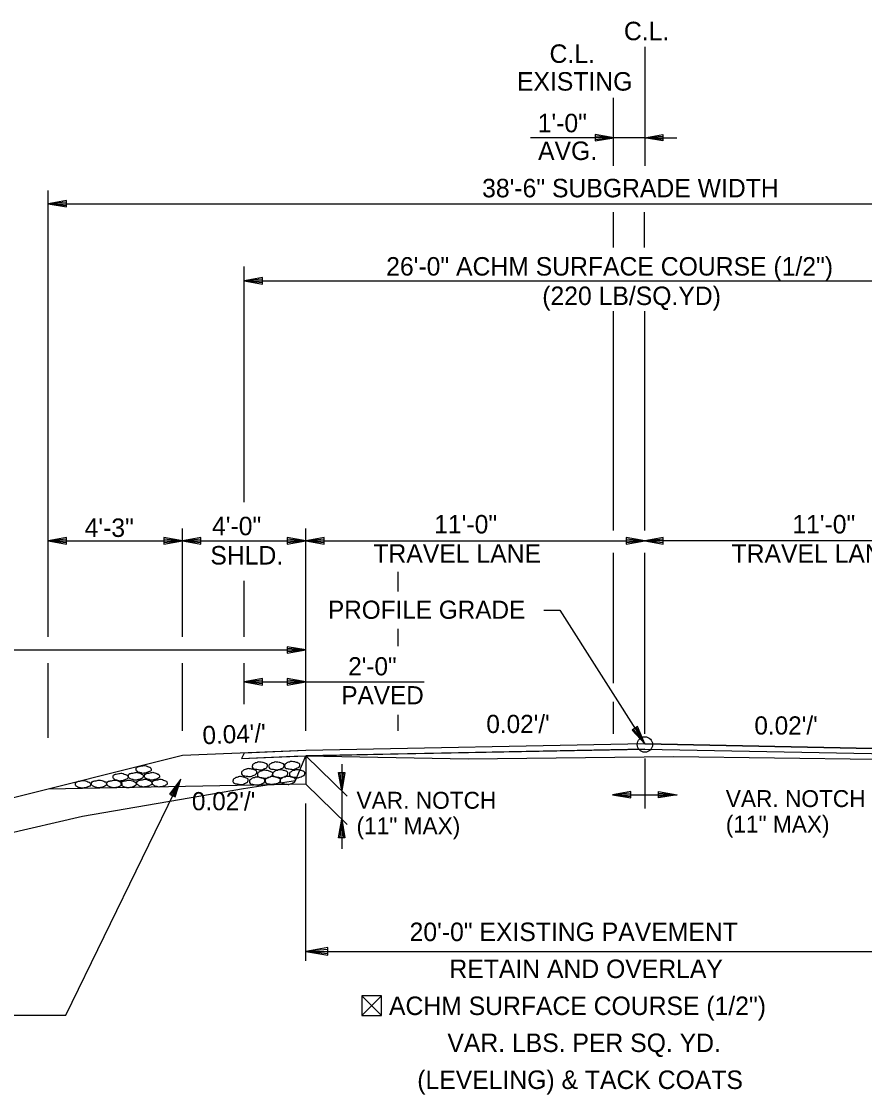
# Model space of a CAD drawing. Extents: x 1461846 to 1462006, y 1686171 to 1686805.
# Drawn here: x 1461905.82 to 1461933.18, y 1686235.49 to 1686270.31 of the extents above; entities that cross this region are included whole.
import ezdxf

# ---------------------------------------------------------------- set-up
doc = ezdxf.new("R2010")
doc.units = 0
for name, color, linetype in [('1', 7, 'Continuous'), ('10', 7, 'Continuous'), ('19', 7, 'Continuous'), ('20', 7, 'Continuous'), ('42', 7, 'Continuous'), ('Level 1', 7, 'Continuous'), ('Level 7', 7, 'Continuous'), ('Level 9', 7, 'Continuous'), ('R_Draft', 7, 'Continuous')]:
    doc.layers.add(name, color=color, linetype=linetype)

# ---------------------------------------------------------------- blocks, each defined once
blk = doc.blocks.new('ROCKS')
at = {"layer": '1'}
blk.add_spline([(0.013, 0.06), (0.053, 0.053), (0.107, 0.033), (0.133, 0.013), (0.133, -0.007), (0.12, -0.033), (0.107, -0.04), (0.073, -0.053), (0.033, -0.067), (0.013, -0.067), (-0.02, -0.06), (-0.06, -0.053), (-0.087, -0.047), (-0.113, -0.02), (-0.113, -0.007), (-0.107, 0.02), (-0.087, 0.033), (-0.067, 0.047), (-0.033, 0.053), (-0.02, 0.06), (0.013, 0.06)], degree=3, dxfattribs=at)
blk = doc.blocks.new('4TO1 ABC')
at = {"layer": '1', "xscale": 0.1312491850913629, "yscale": 0.1312491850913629, "rotation": 180}
for p in [(0.00175, -0.00875), (-0.016625, -0.023625), (0.018375, -0.023625), (0.051625, -0.025375), (-0.03325, -0.0385), (0, -0.0385), (0.034125, -0.04025), (0.06475, -0.04025), (0.098, -0.04025), (0.133, -0.041125)]:
    blk.add_blockref('ROCKS', p, dxfattribs=at)

msp = doc.modelspace()

# ---------------------------------------------------------------- linework, layer by layer
at = {"layer": '10'}
for p, q in [((1461916.861, 1686238.694), (1461917.502, 1686238.053)), ((1461917.502, 1686238.694), (1461916.861, 1686238.053))]:
    msp.add_line(p, q, dxfattribs=at)
msp.add_lwpolyline([(1461917.253, 1686238.053), (1461917.502, 1686238.053), (1461917.502, 1686238.694), (1461916.861, 1686238.694), (1461916.861, 1686238.053), (1461917.242, 1686238.053)], dxfattribs=at)
at = {"layer": '19'}
for p, q in [((1461926.058, 1686265.626), (1461926.058, 1686269.495)), ((1461907.286, 1686264.503), (1461906.686, 1686264.398)), ((1461906.686, 1686264.398), (1461945.406, 1686264.398)), ((1461906.686, 1686264.398), (1461907.286, 1686264.293)), ((1461907.286, 1686264.448), (1461906.846, 1686264.413)), ((1461906.846, 1686264.383), (1461907.286, 1686264.343)), ((1461907.286, 1686264.293), (1461907.286, 1686264.503)), ((1461926.034, 1686262.982), (1461926.034, 1686264.129)), ((1461913.646, 1686262.003), (1461913.046, 1686261.898)), ((1461913.046, 1686261.898), (1461939.046, 1686261.898)), ((1461913.046, 1686261.898), (1461913.646, 1686261.793)), ((1461913.646, 1686261.948), (1461913.206, 1686261.913)), ((1461913.206, 1686261.883), (1461913.646, 1686261.843)), ((1461913.646, 1686261.793), (1461913.646, 1686262.003)), ((1461907.286, 1686253.562), (1461906.686, 1686253.457)), ((1461907.286, 1686253.507), (1461906.846, 1686253.472)), ((1461907.286, 1686253.352), (1461907.286, 1686253.562)), ((1461910.446, 1686253.562), (1461910.446, 1686253.352)), ((1461911.046, 1686253.457), (1461910.446, 1686253.562)), ((1461910.886, 1686253.472), (1461910.446, 1686253.507)), ((1461911.646, 1686253.562), (1461911.046, 1686253.457)), ((1461911.646, 1686253.507), (1461911.206, 1686253.472)), ((1461911.646, 1686253.352), (1461911.646, 1686253.562)), ((1461914.446, 1686253.562), (1461914.446, 1686253.352)), ((1461915.046, 1686253.457), (1461914.446, 1686253.562)), ((1461914.886, 1686253.472), (1461914.446, 1686253.507)), ((1461915.646, 1686253.562), (1461915.046, 1686253.457)), ((1461915.646, 1686253.507), (1461915.206, 1686253.472)), ((1461915.646, 1686253.352), (1461915.646, 1686253.562)), ((1461925.446, 1686253.562), (1461925.446, 1686253.352)), ((1461926.046, 1686253.457), (1461925.446, 1686253.562)), ((1461925.886, 1686253.472), (1461925.446, 1686253.507)), ((1461926.646, 1686253.562), (1461926.046, 1686253.457)), ((1461926.646, 1686253.507), (1461926.206, 1686253.472)), ((1461926.646, 1686253.352), (1461926.646, 1686253.562)), ((1461906.686, 1686253.457), (1461907.286, 1686253.352)), ((1461906.846, 1686253.442), (1461907.286, 1686253.402)), ((1461910.446, 1686253.352), (1461911.046, 1686253.457)), ((1461910.446, 1686253.402), (1461910.886, 1686253.442)), ((1461911.046, 1686253.457), (1461911.646, 1686253.352)), ((1461911.206, 1686253.442), (1461911.646, 1686253.402)), ((1461914.446, 1686253.352), (1461915.046, 1686253.457)), ((1461914.446, 1686253.402), (1461914.886, 1686253.442)), ((1461915.046, 1686253.457), (1461915.646, 1686253.352)), ((1461915.206, 1686253.442), (1461915.646, 1686253.402)), ((1461925.446, 1686253.352), (1461926.046, 1686253.457)), ((1461925.446, 1686253.402), (1461925.886, 1686253.442)), ((1461926.046, 1686253.457), (1461926.646, 1686253.352)), ((1461926.206, 1686253.442), (1461926.646, 1686253.402)), ((1461914.446, 1686250.022), (1461914.446, 1686249.812)), ((1461915.046, 1686249.917), (1461914.446, 1686250.022)), ((1461914.886, 1686249.932), (1461914.446, 1686249.967)), ((1461914.446, 1686249.812), (1461915.046, 1686249.917)), ((1461914.446, 1686249.862), (1461914.886, 1686249.902)), ((1461913.646, 1686248.986), (1461913.046, 1686248.881)), ((1461913.646, 1686248.776), (1461913.646, 1686248.986)), ((1461914.446, 1686248.986), (1461914.446, 1686248.776)), ((1461915.046, 1686248.881), (1461914.446, 1686248.986)), ((1461913.046, 1686248.881), (1461918.889, 1686248.881)), ((1461913.046, 1686248.881), (1461913.646, 1686248.776)), ((1461913.646, 1686248.931), (1461913.206, 1686248.896)), ((1461913.206, 1686248.866), (1461913.646, 1686248.826)), ((1461914.886, 1686248.896), (1461914.446, 1686248.931)), ((1461914.446, 1686248.776), (1461915.046, 1686248.881)), ((1461914.446, 1686248.826), (1461914.886, 1686248.866)), ((1461925.807, 1686247.428), (1461925.632, 1686247.314)), ((1461925.632, 1686247.314), (1461926.046, 1686246.868)), ((1461925.672, 1686247.336), (1461925.946, 1686246.995)), ((1461925.968, 1686247.007), (1461925.764, 1686247.395)), ((1461926.046, 1686246.868), (1461925.807, 1686247.428)), ((1461913.046, 1686246.568), (1461912.961, 1686246.398)), ((1461913.046, 1686246.568), (1461912.961, 1686246.398)), ((1461915.046, 1686246.648), (1461913.046, 1686246.568)), ((1461926.046, 1686246.868), (1461915.046, 1686246.648)), ((1461926.046, 1686246.701), (1461915.046, 1686246.481)), ((1461937.046, 1686246.648), (1461926.046, 1686246.868)), ((1461926.046, 1686246.701), (1461937.046, 1686246.481)), ((1461912.961, 1686246.398), (1461915.046, 1686246.481)), ((1461915.046, 1686246.481), (1461915.046, 1686245.565)), ((1461916.108, 1686245.939), (1461916.318, 1686245.939)), ((1461916.213, 1686245.339), (1461916.108, 1686245.939)), ((1461916.198, 1686245.499), (1461916.158, 1686245.939)), ((1461916.318, 1686245.939), (1461916.213, 1686245.339)), ((1461916.263, 1686245.939), (1461916.228, 1686245.499)), ((1461907.262, 1686238.068), (1461910.99, 1686245.726)), ((1461910.99, 1686245.726), (1461910.626, 1686245.238)), ((1461910.907, 1686245.59), (1461910.675, 1686245.216)), ((1461910.769, 1686245.168), (1461910.932, 1686245.577)), ((1461910.813, 1686245.145), (1461910.99, 1686245.726)), ((1461910.626, 1686245.238), (1461910.813, 1686245.145)), ((1461916.108, 1686243.822), (1461916.213, 1686244.422)), ((1461916.163, 1686243.822), (1461916.198, 1686244.262)), ((1461916.213, 1686244.422), (1461916.318, 1686243.822)), ((1461916.228, 1686244.262), (1461916.268, 1686243.822)), ((1461916.318, 1686243.822), (1461916.108, 1686243.822)), ((1461903.064, 1686238.068), (1461907.262, 1686238.068))]:
    msp.add_line(p, q, dxfattribs=at)
for points in [[(1461922.775, 1686251.211), (1461923.293, 1686251.211), (1461926.046, 1686246.868)], [(1461915.046, 1686246.481), (1461918.046, 1686246.541), (1461926.046, 1686246.701)], [(1461912.961, 1686246.398), (1461913.683, 1686246.427), (1461914.667, 1686246.466), (1461915.046, 1686246.481)]]:
    msp.add_lwpolyline(points, dxfattribs=at)
msp.add_circle((1461926.05, 1686246.849), 0.25, dxfattribs=at)
at = {"layer": '20'}
for p, q in [((1461915.046, 1686246.481), (1461916.39, 1686245.166)), ((1461915.046, 1686245.565), (1461916.39, 1686244.249)), ((1461915.046, 1686239.832), (1461915.046, 1686244.931)), ((1461915.761, 1686240.257), (1461915.046, 1686240.132)), ((1461915.046, 1686240.132), (1461915.761, 1686240.006)), ((1461915.046, 1686240.132), (1461935.046, 1686240.132)), ((1461915.761, 1686240.191), (1461915.237, 1686240.149)), ((1461915.237, 1686240.114), (1461915.761, 1686240.066)), ((1461915.761, 1686240.006), (1461915.761, 1686240.257))]:
    msp.add_line(p, q, dxfattribs=at)
msp.add_lwpolyline([(1461916.213, 1686246.215), (1461916.213, 1686243.465)], dxfattribs=at)
at = {"layer": '42'}
for p, q in [((1461926.046, 1686246.399), (1461926.046, 1686244.767)), ((1461925.598, 1686245.324), (1461924.998, 1686245.219)), ((1461924.998, 1686245.219), (1461925.598, 1686245.114)), ((1461924.998, 1686245.219), (1461927.093, 1686245.219)), ((1461925.598, 1686245.269), (1461925.158, 1686245.234)), ((1461925.158, 1686245.204), (1461925.598, 1686245.164)), ((1461925.598, 1686245.114), (1461925.598, 1686245.324)), ((1461926.493, 1686245.114), (1461926.493, 1686245.324)), ((1461926.493, 1686245.324), (1461927.093, 1686245.219)), ((1461926.493, 1686245.269), (1461926.933, 1686245.234)), ((1461927.093, 1686245.219), (1461926.493, 1686245.114)), ((1461926.933, 1686245.204), (1461926.493, 1686245.164))]:
    msp.add_line(p, q, dxfattribs=at)
at = {"layer": 'Level 7'}
for p, q in [((1461926.045, 1686254.861), (1461926.045, 1686260.908)), ((1461926.045, 1686253.792), (1461926.045, 1686254.861)), ((1461926.045, 1686247.189), (1461926.045, 1686253.071))]:
    msp.add_line(p, q, dxfattribs=at)
at = {"layer": 'Level 9'}
for p, q in [((1461906.686, 1686250.346), (1461906.686, 1686264.824)), ((1461913.046, 1686255.675), (1461913.046, 1686262.366)), ((1461906.686, 1686256.912), (1461906.686, 1686258.245)), ((1461913.046, 1686254.714), (1461913.046, 1686255.675)), ((1461906.686, 1686250.346), (1461906.686, 1686254.697)), ((1461911.046, 1686250.346), (1461911.046, 1686253.86)), ((1461915.046, 1686247.293), (1461915.046, 1686253.86)), ((1461906.686, 1686253.457), (1461915.046, 1686253.457)), ((1461915.046, 1686253.457), (1461926.046, 1686253.457)), ((1461937.046, 1686253.457), (1461926.046, 1686253.457)), ((1461913.046, 1686250.346), (1461913.046, 1686252.159)), ((1461918.046, 1686251.815), (1461918.046, 1686252.456)), ((1461918.046, 1686250.043), (1461918.046, 1686250.607)), ((1461891.046, 1686249.917), (1461915.046, 1686249.917)), ((1461906.686, 1686247.061), (1461906.686, 1686249.485)), ((1461911.046, 1686247.293), (1461911.046, 1686249.485)), ((1461913.046, 1686248.152), (1461913.046, 1686249.485)), ((1461918.046, 1686247.293), (1461918.046, 1686247.806))]:
    msp.add_line(p, q, dxfattribs=at)
at = {"layer": 'R_Draft'}
for p, q in [((1461925.034, 1686265.626), (1461925.034, 1686267.832)), ((1461924.034, 1686266.54), (1461922.334, 1686266.54)), ((1461926.034, 1686266.54), (1461924.034, 1686266.54)), ((1461924.44, 1686266.645), (1461924.44, 1686266.435)), ((1461925.04, 1686266.54), (1461924.44, 1686266.645)), ((1461924.88, 1686266.555), (1461924.44, 1686266.59)), ((1461924.44, 1686266.435), (1461925.04, 1686266.54)), ((1461924.44, 1686266.485), (1461924.88, 1686266.525)), ((1461926.034, 1686266.54), (1461926.634, 1686266.645)), ((1461926.634, 1686266.435), (1461926.034, 1686266.54)), ((1461926.034, 1686266.54), (1461927.087, 1686266.54)), ((1461926.194, 1686266.555), (1461926.634, 1686266.59)), ((1461926.634, 1686266.485), (1461926.194, 1686266.525)), ((1461926.634, 1686266.645), (1461926.634, 1686266.435)), ((1461925.034, 1686262.982), (1461925.034, 1686264.129)), ((1461925.034, 1686254.861), (1461925.034, 1686260.908)), ((1461925.034, 1686253.792), (1461925.034, 1686254.861)), ((1461925.034, 1686248.84), (1461925.034, 1686253.071)), ((1461925.034, 1686247.189), (1461925.034, 1686248.232)), ((1461915.046, 1686246.648), (1461911.046, 1686246.488)), ((1461926.046, 1686246.868), (1461915.046, 1686246.648)), ((1461926.046, 1686246.868), (1461937.046, 1686246.648)), ((1461926.046, 1686246.701), (1461937.046, 1686246.481)), ((1461911.046, 1686246.488), (1461891.046, 1686241.488)), ((1461915.046, 1686245.565), (1461906.684, 1686245.397))]:
    msp.add_line(p, q, dxfattribs=at)
msp.add_lwpolyline([(1461898.954, 1686241.476), (1461905.286, 1686243.936), (1461907.805, 1686244.527), (1461913.029, 1686245.425), (1461914.716, 1686245.68), (1461915.046, 1686246.481), (1461920.316, 1686246.387), (1461926.976, 1686246.462), (1461933.536, 1686246.367), (1461935.046, 1686246.521), (1461937.792, 1686245.91), (1461938.868, 1686245.881), (1461962.881, 1686248.455)], dxfattribs=at)

# ---------------------------------------------------------------- block references
at = {"layer": '19', "xscale": 14.999970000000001, "yscale": -14.999970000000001, "rotation": 180}
msp.add_blockref('4TO1 ABC', (1461909.79, 1686246.166), dxfattribs=at)
at = {"layer": 'Level 1', "xscale": 2.011654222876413, "yscale": 2.011654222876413, "rotation": 1.8263814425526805}
for p in [(1461913.539, 1686246.158), (1461914.079, 1686246.158), (1461914.588, 1686246.174), (1461913.188, 1686245.94), (1461913.703, 1686245.889), (1461914.199, 1686245.905), (1461914.747, 1686245.905), (1461912.912, 1686245.683), (1461913.449, 1686245.666), (1461913.952, 1686245.684), (1461914.443, 1686245.688)]:
    msp.add_blockref('ROCKS', p, dxfattribs=at)

# ---------------------------------------------------------------- texts
at = {"layer": '10'}
for s, height, p in [('VAR. NOTCH', 0.55, (1461916.694, 1686244.762)), ('VAR. NOTCH', 0.55, (1461928.675, 1686244.817)), ('(11" MAX)', 0.55, (1461916.694, 1686243.933)), ('(11" MAX)', 0.55, (1461928.675, 1686243.988)), ('20\'-0" EXISTING PAVEMENT', 0.6, (1461918.416, 1686240.468)), ('RETAIN AND OVERLAY', 0.6, (1461919.708, 1686239.268)), ('ACHM SURFACE COURSE (1/2")', 0.6, (1461917.747, 1686238.068)), ('VAR. LBS. PER SQ. YD.', 0.6, (1461919.642, 1686236.868)), ('(LEVELING) & TACK COATS', 0.6, (1461918.664, 1686235.668))]:
    msp.add_text(s, height=height, dxfattribs=at).set_placement(p)
at = {"layer": '19'}
for s, height, rotation, p in [('4\'-3"', 0.6, 360, (1461907.871, 1686253.584)), ('2\'-0"', 0.59, 360, (1461916.424, 1686249.092)), ('PAVED', 0.59, 360, (1461916.201, 1686248.152)), ("0.02'/'", 0.59, 360, (1461920.906, 1686247.221)), ("0.02'/'", 0.59, 360, (1461929.603, 1686247.171)), ("0.04'/'", 0.59, 2.1602, (1461911.706, 1686246.854)), ("0.02'/'", 0.59, 360, (1461911.354, 1686244.714))]:
    msp.add_text(s, height=height, rotation=rotation, dxfattribs=at).set_placement(p)
msp.add_text('PROFILE GRADE', height=0.59001, dxfattribs=at).set_placement((1461915.768, 1686250.927))
at = {"layer": '42'}
for s, height, p in [('38\'-6" SUBGRADE WIDTH', 0.60001, (1461920.769, 1686264.606)), ('26\'-0" ACHM SURFACE COURSE (1/2")', 0.60001, (1461917.656, 1686262.066)), ('(220 LB/SQ.YD)', 0.60001, (1461922.72, 1686261.11)), ('4\'-0"', 0.6, (1461912.005, 1686253.639)), ('11\'-0"', 0.6, (1461919.213, 1686253.697)), ('11\'-0"', 0.6, (1461930.833, 1686253.697)), ('SHLD.', 0.6, (1461911.951, 1686252.689)), ('TRAVEL LANE', 0.6, (1461917.24, 1686252.747)), ('TRAVEL LANE', 0.6, (1461928.861, 1686252.747))]:
    msp.add_text(s, height=height, rotation=360, dxfattribs=at).set_placement(p)
at = {"layer": 'R_Draft'}
msp.add_text('C.L.', height=0.6, rotation=360, dxfattribs=at).set_placement((1461925.369, 1686269.704))
for s, p in [('C.L.', (1461922.956, 1686268.969)), ('EXISTING', (1461921.9, 1686268.069)), ('1\'-0"', (1461922.572, 1686266.717)), ('AVG.', (1461922.584, 1686265.817))]:
    msp.add_text(s, height=0.6, dxfattribs=at).set_placement(p)

doc.saveas('drawing.dxf')
